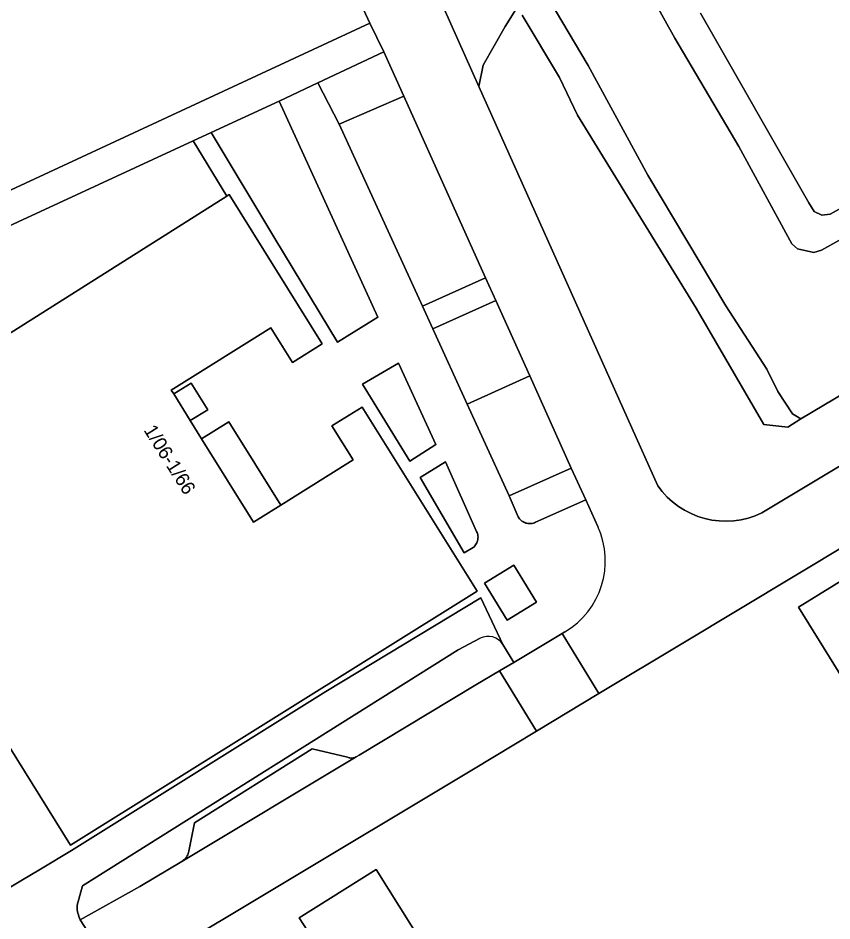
# Model space of a CAD drawing. Extents: x 162788 to 163838, y 385791 to 386523.
# Drawn here: x 163143.1 to 163202.2, y 386178.4 to 386243.9 of the extents above; entities that cross this region are included whole.
import ezdxf

# ---------------------------------------------------------------- set-up
doc = ezdxf.new("R2010")
doc.units = 0
for name, color, linetype in [('IMGEO_Berm_groen', 7, 'Continuous'), ('IMGEO_Erf', 7, 'Continuous'), ('IMGEO_Groenvoorziening', 7, 'Continuous'), ('IMGEO_Oever', 7, 'Continuous'), ('IMGEO_Pand', 7, 'Continuous'), ('IMGEO_Pand_nummerreeks', 7, 'Continuous'), ('IMGEO_Parkeervlak_halfverhard', 7, 'Continuous'), ('IMGEO_Parkeervlak_open', 7, 'Continuous'), ('IMGEO_Rijbaan_lokaal_gesloten', 7, 'Continuous'), ('IMGEO_Voetpad_open', 7, 'Continuous'), ('IMGEO_Waterloop', 7, 'Continuous'), ('IMGEO_Woonerf_gesloten', 7, 'Continuous'), ('IMGEO_Woonerf_open', 7, 'Continuous')]:
    doc.layers.add(name, color=color, linetype=linetype)

msp = doc.modelspace()

# ---------------------------------------------------------------- linework, layer by layer
at = {"layer": 'IMGEO_Berm_groen'}
msp.add_lwpolyline([(163176.655, 386198.928), (163175.048, 386198.079), (163147.799, 386180.973), (163147.417, 386179.563), (163147.41, 386179.448), (163147.411, 386179.33), (163147.421, 386179.21), (163147.438, 386179.089), (163147.463, 386178.968), (163147.495, 386178.848), (163147.535, 386178.731), (163147.582, 386178.616), (163147.636, 386178.505), (163151.955, 386180.913), (163155.014, 386182.729), (163155.09, 386182.782), (163155.161, 386182.841), (163155.227, 386182.906), (163155.288, 386182.976), (163155.342, 386183.05), (163155.39, 386183.13), (163155.432, 386183.212), (163155.466, 386183.298), (163155.493, 386183.387), (163155.513, 386183.477), (163155.931, 386185.543), (163164.465, 386190.917), (163167.029, 386190.292), (163167.084, 386190.271), (163167.141, 386190.254), (163167.199, 386190.243), (163167.258, 386190.236), (163167.317, 386190.234), (163167.376, 386190.237), (163167.434, 386190.245), (163167.492, 386190.258), (163167.549, 386190.276), (163167.603, 386190.298), (163167.656, 386190.325), (163167.706, 386190.356), (163167.872, 386190.449), (163176.343, 386195.547), (163178.061, 386196.569), (163179.093, 386197.182), (163178.307, 386198.473)], dxfattribs=at)
msp.add_arc((163177.239, 386197.822), 1.25, 31.35178, 117.85058, dxfattribs=at)
at = {"layer": 'IMGEO_Erf'}
for points in [[(163130.613, 386225.913), (163168.646, 386243.581), (163165.661, 386250), (163160.64, 386260.798), (163150.79, 386288.192), (163147.952, 386293.692), (163146.394, 386296.272), (163137.48, 386307.693)], [(163192.642, 386244.303), (163200.495, 386230.524), (163200.895, 386229.904), (163201.455, 386229.643), (163202.054, 386229.702), (163238.524, 386250)], [(163219.801, 386215.69), (163191.373, 386198.584), (163185.274, 386194.916), (163180.732, 386192.184), (163176.051, 386189.368), (163174.351, 386188.349), (163152.119, 386175.015)], [(163164.137, 386177.674), (163163.53, 386178.648), (163169.112, 386182.147), (163176.671, 386170.084)]]:
    msp.add_lwpolyline(points, dxfattribs=at)
for points in [[(163158.272, 386231.019), (163155.822, 386235.03), (163136.265, 386225.973), (163132.742, 386224.346), (163130.49, 386223.107), (163129.798, 386222.597), (163128.425, 386221.273), (163127.432, 386220.241), (163126.527, 386219.13), (163125.719, 386217.947), (163125.011, 386216.702), (163124.41, 386215.401), (163124.091, 386214.262), (163123.871, 386213.1), (163123.75, 386211.924), (163123.73, 386210.741), (163123.811, 386209.561), (163123.855, 386209.277), (163126.716, 386211.085), (163130.877, 386213.714)], [(163206.709, 386189.99), (163199.766, 386201.175), (163204.937, 386204.385), (163205.709, 386203.143), (163212.338, 386207.258), (163211.603, 386208.442), (163216.867, 386211.71), (163223.774, 386200.583)]]:
    msp.add_lwpolyline(points, close=True, dxfattribs=at)
at = {"layer": 'IMGEO_Groenvoorziening'}
for points in [[(163179.353, 386244.767), (163178.469, 386243.332), (163176.879, 386240.518), (163176.558, 386238.969), (163189.543, 386209.993), (163189.866, 386209.572), (163190.225, 386209.181), (163190.617, 386208.823), (163191.039, 386208.502), (163191.487, 386208.218), (163191.959, 386207.976), (163192.451, 386207.776), (163192.958, 386207.62), (163193.477, 386207.509), (163194.003, 386207.445), (163194.534, 386207.427), (163195.063, 386207.456), (163195.589, 386207.531), (163196.105, 386207.653), (163196.609, 386207.82), (163197.096, 386208.03), (163227.747, 386226.411), (163301.902, 386270.889)], [(163264.496, 386250), (163252.47, 386242.879), (163245.673, 386238.586), (163238.157, 386234.593), (163232.379, 386231.28), (163228.241, 386228.664), (163222.344, 386225.65), (163212.188, 386219.1), (163209.849, 386217.823), (163205.691, 386215.147), (163205.331, 386215.447), (163204.032, 386217.307), (163199.927, 386214.856), (163198.974, 386214.253), (163197.235, 386214.454), (163192.319, 386222.893)], [(163192.319, 386222.893), (163183.725, 386236.893), (163182.406, 386239.632), (163179.693, 386244.156)]]:
    msp.add_lwpolyline(points, dxfattribs=at)
for points in [[(163169.666, 386241.487), (163164.886, 386239.249), (163166.415, 386236.248), (163171.111, 386238.28)], [(163162.069, 386237.922), (163157.126, 386235.633), (163161.766, 386227.947), (163166.305, 386220.428), (163169.224, 386222.243)], [(163170.732, 386218.904), (163168.109, 386217.379), (163171.554, 386211.775), (163173.43, 386212.992)], [(163174.137, 386211.728), (163172.302, 386210.609), (163175.505, 386205.128), (163176.152, 386205.513), (163176.215, 386205.571), (163176.274, 386205.634), (163176.326, 386205.703), (163176.372, 386205.775), (163176.411, 386205.852), (163176.443, 386205.931), (163176.468, 386206.013), (163176.486, 386206.097), (163176.496, 386206.183), (163176.499, 386206.269), (163176.494, 386206.354), (163176.481, 386206.439), (163176.461, 386206.523), (163176.433, 386206.604), (163176.399, 386206.683)], [(163183.266, 386211.268), (163178.77, 386209.257), (163179.419, 386207.742), (163179.461, 386207.673), (163179.508, 386207.608), (163179.56, 386207.547), (163179.617, 386207.49), (163179.679, 386207.439), (163179.746, 386207.394), (163179.815, 386207.354), (163179.888, 386207.32), (163179.964, 386207.293), (163180.042, 386207.272), (163180.121, 386207.258), (163180.201, 386207.251), (163180.281, 386207.25), (163180.361, 386207.257), (163180.441, 386207.27), (163180.518, 386207.29), (163180.594, 386207.317), (163180.667, 386207.35), (163184.316, 386208.966)], [(163176.973, 386202.93), (163178.626, 386200.249), (163180.755, 386201.561), (163179.102, 386204.242)]]:
    msp.add_lwpolyline(points, close=True, dxfattribs=at)
at = {"layer": 'IMGEO_Oever'}
for points in [[(163276.832, 386311.461), (163279.76, 386304.643), (163280.519, 386303.163), (163282.076, 386299.042), (163282.711, 386297.567), (163284.129, 386298.223), (163285.262, 386295.571), (163283.842, 386294.937), (163285.213, 386290.763), (163289.29, 386279.827), (163289.571, 386278.548), (163289.291, 386277.988), (163288.891, 386277.589), (163278.138, 386271.642), (163263.566, 386263.938), (163238.524, 386250), (163202.054, 386229.702), (163201.455, 386229.643), (163200.895, 386229.904), (163200.495, 386230.524), (163192.642, 386244.303)], [(163187.14, 386249.053), (163190.782, 386242.484), (163195.418, 386234.625), (163199.276, 386227.566), (163199.696, 386227.185), (163200.875, 386226.925), (163201.415, 386227.105), (163242.438, 386250)], [(163179.693, 386244.156), (163182.406, 386239.632), (163183.725, 386236.893), (163192.319, 386222.893), (163197.235, 386214.454), (163198.974, 386214.253), (163199.927, 386214.856), (163199.314, 386215.212), (163198.255, 386216.851), (163197.455, 386218.471), (163194.477, 386223.052), (163188.822, 386232.551), (163184.505, 386240.51), (163181.209, 386246.069)]]:
    msp.add_lwpolyline(points, dxfattribs=at)
at = {"layer": 'IMGEO_Pand'}
for points in [[(163140.23, 386194.667), (163146.919, 386183.911), (163176.433, 386202.339), (163168.082, 386215.712), (163165.892, 386214.344), (163167.435, 386211.874), (163162.181, 386208.594), (163160.218, 386207.368), (163156.444, 386213.413), (163155.62, 386214.732), (163154.413, 386216.666), (163154.241, 386216.941), (163161.464, 386221.451), (163163.025, 386218.95), (163165.196, 386220.305), (163158.439, 386231.125), (163158.272, 386231.019), (163130.877, 386213.714)], [(163176.671, 386170.084), (163169.112, 386182.147), (163163.53, 386178.648), (163164.137, 386177.674)]]:
    msp.add_lwpolyline(points, dxfattribs=at)
for points in [[(163154.413, 386216.666), (163155.62, 386214.732), (163156.88, 386215.518), (163155.672, 386217.453)], [(163156.444, 386213.413), (163160.218, 386207.368), (163162.181, 386208.594), (163158.407, 386214.638)], [(163223.774, 386200.583), (163216.867, 386211.71), (163211.603, 386208.442), (163212.338, 386207.258), (163205.709, 386203.143), (163204.937, 386204.385), (163199.766, 386201.175), (163206.709, 386189.99)]]:
    msp.add_lwpolyline(points, close=True, dxfattribs=at)
at = {"layer": 'IMGEO_Parkeervlak_halfverhard'}
for points in [[(163172.469, 386223.023), (163177.049, 386225.084), (163171.111, 386238.28), (163166.415, 386236.248)], [(163177.788, 386223.442), (163173.218, 386221.386), (163175.715, 386215.93), (163180.25, 386217.971)]]:
    msp.add_lwpolyline(points, close=True, dxfattribs=at)
at = {"layer": 'IMGEO_Parkeervlak_open'}
for points in [[(163177.049, 386225.084), (163172.469, 386223.023), (163173.218, 386221.386), (163177.788, 386223.442)], [(163175.715, 386215.93), (163178.77, 386209.257), (163183.266, 386211.268), (163180.25, 386217.971)], [(163167.656, 386190.325), (163167.603, 386190.298), (163167.549, 386190.276), (163167.492, 386190.258), (163167.434, 386190.245), (163167.376, 386190.237), (163167.317, 386190.234), (163167.258, 386190.236), (163167.199, 386190.243), (163167.141, 386190.254), (163167.084, 386190.271), (163167.029, 386190.292), (163164.465, 386190.917), (163155.931, 386185.543), (163155.513, 386183.477), (163155.493, 386183.387), (163155.466, 386183.298), (163155.432, 386183.212), (163155.39, 386183.13), (163155.342, 386183.05), (163155.288, 386182.976), (163155.227, 386182.906), (163155.161, 386182.841), (163155.09, 386182.782), (163155.014, 386182.729)]]:
    msp.add_lwpolyline(points, close=True, dxfattribs=at)
at = {"layer": 'IMGEO_Rijbaan_lokaal_gesloten'}
msp.add_lwpolyline([(163177.302, 386248.448), (163173.751, 386248.639), (163173.01, 386248.788), (163171.995, 386249.221), (163176.558, 386238.969), (163176.879, 386240.518), (163178.469, 386243.332), (163179.353, 386244.767)], close=True, dxfattribs=at)
at = {"layer": 'IMGEO_Voetpad_open'}
for points in [[(163184.316, 386208.966), (163180.667, 386207.35), (163180.594, 386207.317), (163180.518, 386207.29), (163180.441, 386207.27), (163180.361, 386207.257), (163180.281, 386207.25), (163180.201, 386207.251), (163180.121, 386207.258), (163180.042, 386207.272), (163179.964, 386207.293), (163179.888, 386207.32), (163179.815, 386207.354), (163179.746, 386207.394), (163179.679, 386207.439), (163179.617, 386207.49), (163179.56, 386207.547), (163179.508, 386207.608), (163179.461, 386207.673), (163179.419, 386207.742), (163178.77, 386209.257), (163175.715, 386215.93), (163173.218, 386221.386), (163172.469, 386223.023), (163166.415, 386236.248), (163164.886, 386239.249), (163162.069, 386237.922), (163169.224, 386222.243), (163166.305, 386220.428), (163161.766, 386227.947), (163157.126, 386235.633), (163155.822, 386235.03), (163158.272, 386231.019), (163158.439, 386231.125), (163165.196, 386220.305), (163163.025, 386218.95), (163161.464, 386221.451), (163154.241, 386216.941), (163154.413, 386216.666), (163155.672, 386217.453), (163156.88, 386215.518), (163155.62, 386214.732), (163156.444, 386213.413), (163158.407, 386214.638), (163162.181, 386208.594), (163167.435, 386211.874), (163165.892, 386214.344), (163168.082, 386215.712), (163176.433, 386202.339), (163146.919, 386183.911), (163140.23, 386194.667)], [(163185.196, 386207.035), (163184.316, 386208.966)], [(163141.284, 386180.105), (163143.33, 386181.33), (163144.744, 386182.176), (163146.996, 386183.521), (163165.457, 386195.061), (163176.708, 386201.869), (163178.307, 386198.473), (163179.093, 386197.182), (163182.617, 386199.278), (163182.804, 386199.389)]]:
    msp.add_lwpolyline(points, dxfattribs=at)
for points in [[(163170.732, 386218.904), (163173.43, 386212.992), (163171.554, 386211.775), (163168.109, 386217.379)], [(163174.137, 386211.728), (163176.399, 386206.683), (163176.433, 386206.604), (163176.461, 386206.523), (163176.481, 386206.439), (163176.494, 386206.354), (163176.499, 386206.269), (163176.496, 386206.183), (163176.486, 386206.097), (163176.468, 386206.013), (163176.443, 386205.931), (163176.411, 386205.852), (163176.372, 386205.775), (163176.326, 386205.703), (163176.274, 386205.634), (163176.215, 386205.571), (163176.152, 386205.513), (163175.505, 386205.128), (163172.302, 386210.609)], [(163176.973, 386202.93), (163179.102, 386204.242), (163180.755, 386201.561), (163178.626, 386200.249)]]:
    msp.add_lwpolyline(points, close=True, dxfattribs=at)
msp.add_arc((163179.737, 386204.546), 6, 300.74367, 24.51244, dxfattribs=at)
at = {"layer": 'IMGEO_Waterloop'}
for points in [[(163269.342, 386264.693), (163262.127, 386260.881), (163242.438, 386250), (163201.415, 386227.105), (163200.875, 386226.925), (163199.696, 386227.185), (163199.276, 386227.566), (163195.418, 386234.625), (163190.782, 386242.484), (163187.14, 386249.053), (163185.759, 386251.758), (163175.833, 386269.654)], [(163181.209, 386246.069), (163184.505, 386240.51), (163188.822, 386232.551), (163194.477, 386223.052), (163197.455, 386218.471), (163198.255, 386216.851), (163199.314, 386215.212), (163199.927, 386214.856), (163204.032, 386217.307), (163217.266, 386225.414), (163233.938, 386235.256), (163237.257, 386236.873), (163250.233, 386244.613)]]:
    msp.add_lwpolyline(points, dxfattribs=at)
at = {"layer": 'IMGEO_Woonerf_gesloten'}
for points in [[(163136.265, 386225.973), (163155.822, 386235.03), (163157.126, 386235.633), (163162.069, 386237.922), (163164.886, 386239.249), (163169.666, 386241.487), (163168.646, 386243.581), (163130.613, 386225.913)], [(163178.307, 386198.473), (163176.708, 386201.869), (163165.457, 386195.061), (163146.996, 386183.521), (163144.744, 386182.176), (163143.33, 386181.33), (163141.284, 386180.105), (163138.639, 386178.987), (163137.001, 386178.435), (163134.705, 386177.857), (163132.65, 386177.467), (163130.247, 386177.153), (163127.655, 386177.119), (163125.633, 386177.232), (163123.102, 386177.607), (163122.294, 386177.794)], [(163150.727, 386173.684), (163147.636, 386178.505), (163147.582, 386178.616), (163147.535, 386178.731), (163147.495, 386178.848), (163147.463, 386178.968), (163147.438, 386179.089), (163147.421, 386179.21), (163147.411, 386179.33), (163147.41, 386179.448), (163147.417, 386179.563), (163147.799, 386180.973), (163175.048, 386198.079), (163176.655, 386198.928)]]:
    msp.add_lwpolyline(points, dxfattribs=at)
msp.add_arc((163177.239, 386197.822), 1.25, 31.35178, 117.85058, dxfattribs=at)
at = {"layer": 'IMGEO_Woonerf_open'}
for points in [[(163137.48, 386307.693), (163146.394, 386296.272), (163147.952, 386293.692), (163150.79, 386288.192), (163160.64, 386260.798), (163165.661, 386250), (163168.646, 386243.581), (163169.666, 386241.487), (163171.111, 386238.28), (163177.049, 386225.084), (163177.788, 386223.442), (163180.25, 386217.971), (163183.266, 386211.268), (163184.316, 386208.966), (163185.196, 386207.035)], [(163301.902, 386270.889), (163227.747, 386226.411), (163197.096, 386208.03), (163196.609, 386207.82), (163196.105, 386207.653), (163195.589, 386207.531), (163195.063, 386207.456), (163194.534, 386207.427), (163194.003, 386207.445), (163193.477, 386207.509), (163192.958, 386207.62), (163192.451, 386207.776), (163191.959, 386207.976), (163191.487, 386208.218), (163191.039, 386208.502), (163190.617, 386208.823), (163190.225, 386209.181), (163189.866, 386209.572), (163189.543, 386209.993), (163176.558, 386238.969), (163171.995, 386249.221)], [(163182.804, 386199.389), (163182.617, 386199.278), (163185.274, 386194.916), (163191.373, 386198.584), (163219.801, 386215.69), (163234.753, 386224.681), (163242.902, 386231.241)]]:
    msp.add_lwpolyline(points, dxfattribs=at)
for points in [[(163182.617, 386199.278), (163179.093, 386197.182), (163178.061, 386196.569), (163180.732, 386192.184), (163185.274, 386194.916)], [(163174.351, 386188.349), (163176.051, 386189.368), (163180.732, 386192.184), (163178.061, 386196.569), (163176.343, 386195.547), (163167.872, 386190.449), (163167.706, 386190.356), (163167.656, 386190.325), (163155.014, 386182.729), (163151.955, 386180.913), (163147.636, 386178.505), (163150.727, 386173.684), (163152.119, 386175.015)]]:
    msp.add_lwpolyline(points, close=True, dxfattribs=at)
msp.add_arc((163179.737, 386204.546), 6, 300.74367, 24.51244, dxfattribs=at)

# ---------------------------------------------------------------- texts
at = {"layer": 'IMGEO_Pand_nummerreeks'}
msp.add_text('1/06-1/66', height=1, rotation=302.29169, dxfattribs=at).set_placement((163152.204, 386214.033))

doc.saveas('drawing.dxf')
